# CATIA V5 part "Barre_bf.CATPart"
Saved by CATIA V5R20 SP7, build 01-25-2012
Part number: Barre_bf
Bounding box of the stored display mesh (mm): x 10 to 20, y -5.999 to 28.653, z 100.223 to 179.204
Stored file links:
  G:\bon\Nouveau dossier\Barre_bf.CATPart
  G:\bon\Nouveau dossier\cgirerd.CATProduct
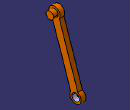
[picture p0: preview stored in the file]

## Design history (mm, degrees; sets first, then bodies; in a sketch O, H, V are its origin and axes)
Set1
  Point1 "B": linked copy from another document
  Point2 "F": linked copy from another document
Body1 (main body)
  Sketch1 on yz-plane, origin (0, 0, 0), H (0, 1, 0), V (0, 0, 1)
    arc A1 centre (0, 173.2051) radius 6 from (5.2219, 170.2502) to (-2.3564, 167.6872) ccw
    point P1 (0, 173.2051)
    reference projected point E1 (0, 173.2051) from Point1
    arc A2 centre (22.6541, 106.2216) radius 6 from (17.4322, 109.1765) to (25.0105, 111.7395) ccw
    point P2 (22.6541, 106.2216)
    reference projected point E2 (22.6541, 106.2216) from Point2
    line L1 (5.2219, 170.2502) -> (25.0105, 111.7395)
    line L2 (-2.3564, 167.6872) -> (17.4322, 109.1765)
    radius A1 = 6
    radius A2 = 6
    distance L1 L2 = 8
    distance P1 L1 = 4
    distance P2 L1 = 4
    coincidence: P1 E1, P2 E2
  Pad1: profile Sketch1, direction (1, 0, 0), length 15, opposite side length -10
  Sketch2 on end face of Pad1, origin (15, 0, 0), H (0, 1, 0), V (0, 0, 1)
    circle A1 centre (22.6541, 106.2216) radius 4
    point P1 (22.6541, 106.2216)
    reference projected point E1 (22.6541, 106.2216) from Point2
    radius A1 = 4
    coincidence: P1 E1
  Pocket1: profile Sketch2, direction (-1, 0, 0), length 5
  Sketch3 on end face of Pad1, origin (15, 0, 0), H (0, 1, 0), V (0, 0, 1)
    circle A1 centre (0, 173.2051) radius 4
    point P1 (0, 173.2051)
    reference projected point E1 (0, 173.2051) from Point1
    radius A1 = 4
    coincidence: P1 E1
  Pad2: profile Sketch3, direction (1, 0, 0), length 5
